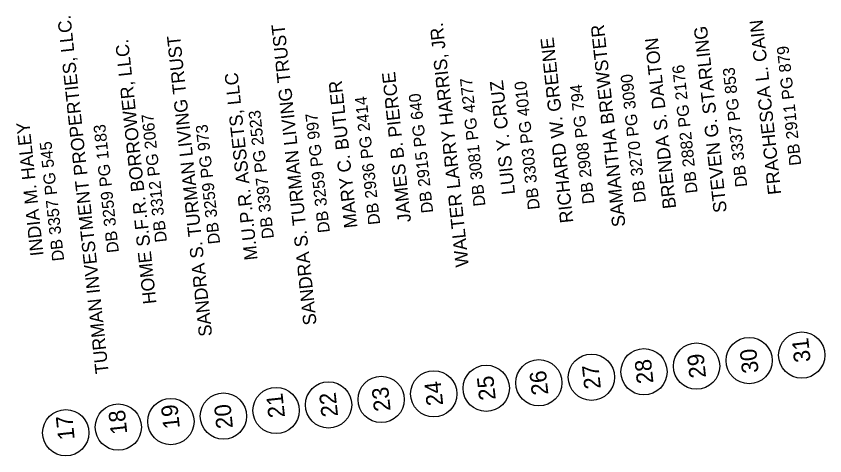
# Model space of a CAD drawing. Extents: x 1611576 to 1617186, y 899279 to 905462.
# Drawn here: x 1615807.5 to 1616113.5, y 902333.4 to 902499.6 of the extents above; entities that cross this region are included whole.
import ezdxf

# ---------------------------------------------------------------- set-up
doc = ezdxf.new("R2010")
doc.units = 0
for name, color, linetype in [('Exist Property Deed Book Text', 7, 'Continuous'), ('Exist Property Owner Number CELL', 7, 'Continuous'), ('Exist Property Owner Text', 7, 'Continuous')]:
    doc.layers.add(name, color=color, linetype=linetype)

msp = doc.modelspace()

# ---------------------------------------------------------------- linework, layer by layer
at = {"layer": 'Exist Property Owner Number CELL'}
for centre in [(1616084.81, 902369.42), (1616104.7, 902371.52), (1616064.92, 902367.33), (1616025.14, 902363.14), (1616045.03, 902365.23), (1616005.25, 902361.04), (1615965.47, 902356.85), (1615985.36, 902358.94), (1615945.58, 902354.75), (1615905.8, 902350.56), (1615925.69, 902352.65), (1615885.91, 902348.46), (1615846.13, 902344.27), (1615866.02, 902346.36), (1615826.24, 902342.17)]:
    msp.add_circle(centre, 8.75, dxfattribs=at)

# ---------------------------------------------------------------- texts
at = {"layer": 'Exist Property Deed Book Text'}
for s, p in [('DB 2911 PG 879', (1616104.55, 902443.39)), ('DB 2882 PG 2176', (1616065.33, 902432.91)), ('DB 3337 PG 853', (1616084.1, 902435.27)), ('DB 3081 PG 4277', (1615985.05, 902427.99)), ('DB 3270 PG 3090', (1616045.8, 902429.41)), ('DB 3303 PG 4010', (1616005.62, 902426.73)), ('DB 2908 PG 794', (1616026.29, 902428.87)), ('DB 2936 PG 2414', (1615945.23, 902421)), ('DB 2915 PG 640', (1615965.29, 902425.42)), ('DB 3397 PG 2523', (1615905.01, 902415.72)), ('DB 3312 PG 2067', (1615864.53, 902414.37)), ('DB 3259 PG 997', (1615926.19, 902417.97)), ('DB 3259 PG 1183', (1615846.36, 902410.41)), ('DB 3259 PG 973', (1615884.67, 902413.68)), ('DB 3357 PG 545', (1615825.65, 902407.26))]:
    msp.add_text(s, height=4.5, rotation=96.118, dxfattribs=at).set_placement(p)
at = {"layer": 'Exist Property Owner Number CELL'}
for s, p in [('31', (1616108.11, 902369.06)), ('29', (1616068.52, 902363.11)), ('30', (1616088.43, 902364.96)), ('28', (1616048.63, 902361.01)), ('26', (1616008.86, 902356.67)), ('27', (1616028.74, 902358.92)), ('25', (1615988.96, 902354.73)), ('23', (1615949.18, 902350.53)), ('24', (1615969.07, 902352.63)), ('21', (1615909.21, 902348.1)), ('22', (1615929.29, 902348.44)), ('18', (1615849.54, 902341.81)), ('19', (1615869.43, 902343.91)), ('20', (1615889.53, 902344)), ('17', (1615829.65, 902339.72))]:
    msp.add_text(s, height=6.25, rotation=96.118, dxfattribs=at).set_placement(p)
at = {"layer": 'Exist Property Owner Text'}
for s, p in [('TURMAN INVESTMENT PROPERTIES, LLC.', (1615842.51, 902364.69)), ('WALTER LARRY HARRIS, JR.', (1615978.76, 902405.08)), ('FRACHESCA L. CAIN', (1616096.98, 902432.41)), ('SANDRA S. TURMAN LIVING TRUST', (1615921.18, 902383.08)), ('SAMANTHA BREWSTER', (1616038.03, 902420.25)), ('STEVEN G. STARLING', (1616076.38, 902425.62)), ('SANDRA S. TURMAN LIVING TRUST', (1615881.66, 902378.81)), ('RICHARD W. GREENE', (1616018.31, 902421.69)), ('BRENDA S. DALTON', (1616057.2, 902427.09)), ('HOME S.F.R. BORROWER, LLC.', (1615860.56, 902391.05)), ('JAMES B. PIERCE', (1615956.91, 902421.97)), ('M.U.P.R. ASSETS, LLC', (1615898.87, 902407.63)), ('LUIS Y. CRUZ', (1615996.26, 902432.41)), ('MARY C. BUTLER', (1615936.61, 902419.78)), ('INDIA M. HALEY', (1615817.86, 902409.22))]:
    msp.add_text(s, height=5, rotation=96.118, dxfattribs=at).set_placement(p)

doc.saveas('drawing.dxf')
